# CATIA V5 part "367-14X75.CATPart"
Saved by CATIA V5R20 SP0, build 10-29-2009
Part number: 367-14X75
Definition: NONE
Nomenclature: 367-14X75
Source: Unknown
Description: 367-14X75
Bounding box of the stored display mesh (mm): x 0 to 75, y -14 to 14, z -14 to 14
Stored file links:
  C:\Users\Utente\Desktop\IO LAVORO\3D X SITO CF\X SITO\PLASTICA\3D files 367\367-14X75.CATPart
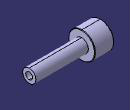
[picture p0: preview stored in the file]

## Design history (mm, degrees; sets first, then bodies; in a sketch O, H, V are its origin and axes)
Body1 "367-14X75" (main body)
  Solid1: solid without history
